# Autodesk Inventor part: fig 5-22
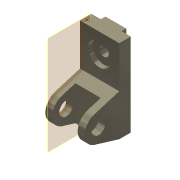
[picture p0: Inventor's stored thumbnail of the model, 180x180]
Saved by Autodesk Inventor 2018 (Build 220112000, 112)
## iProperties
Shininess: 65.0
Angle Display Precision: 2
Document Length Units: 11269
Document Angle Units: 11279
Document Time Units: 11290
Document Mass Units: 11283
Document Length Units Precision: 3
Document Angle Units Precision: 2
Compacted: False
Created: 2001-11
Part Number: fig 5-22
Document SubType Name: Modeling
Designer: Renu Muthoo
Density: 1 g/cm^3
Material: Generic
Appearance: Metal-Titanium (Polished)
Density: 0.0
Volumn: 0.0
Area: 0.0
PropertySet Name: Model Information
Control State: 0
Master: False
Checked Out: False
Author: Renu Muthoo
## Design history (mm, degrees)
node "Sketch1"
sketch "Sketch2"
  geometry: L1 (33.257, 104.664)-(33.257, -75.336); L2 (33.257, -75.336)-(8.257, -75.336); L3 (8.257, -75.336)-(-45.451, -59.045); L4 (-45.451, -1.628)-(8.257, 14.664); L5 (8.257, 14.664)-(8.257, 104.664); L6 (8.257, 104.664)-(33.257, 104.664); C1 r 15 at (-36.743, -30.336); A1 r 30 centre (-36.743, -30.336) between (-45.451, -1.628) and (-45.451, -59.045)
  constraints: 12 end point, 2 centre point, 2 equal length, 2 parallel, 2 point on circle, 2 tangent, 1 coincident, 1 perpendicular, 1 vertical
  dimensions: "d0" = 180 distance of L1.start L1.end; "d1" = 30 radius of A1; "d2" = 25 distance of L5.end L1.start; "d3" = 45 distance from line of L2 A1.centre; "d4" = 70 distance from line of L1 A1.centre; "d5" = 30 diameter of C1
extrude "Extrusion1" new body sketch "Sketch2" distance "d6" = 85; taper "d7" = 0 deg
workplane "Work Plane1"
sketch "Sketch3"
  geometry: L1 (15, 62.364)-(70, 62.364); L2 (70, 62.364)-(70, -52.386); L3 (70, -52.386)-(15, -52.386); L4 (15, -52.386)-(15, 62.364); L5 (0, -45)-(0, -28.708) reference
  constraints: 8 end point, 2 parallel, 1 horizontal, 1 perpendicular
  dimensions: "d8" = 55 distance of L1.start L1.end; "d9" = 15 distance between parallel lines of L5 L4
extrude "Extrusion2" cut sketch "Sketch3" distance "d10" = 50; taper "d11" = 0 deg
sketch "Sketch4"
  geometry: L1 (0, 25)-(85, 25) reference; L2 (0, 0)-(0, 25) reference; L3 (20, 25)-(65, 25); L4 (65, 25)-(65, 35); L5 (65, 35)-(20, 35); L6 (20, 35)-(20, 25)
  constraints: 8 end point, 2 parallel, 1 horizontal, 1 perpendicular, 1 point on line
  dimensions: "d12" = 45 distance of L4.end L5.end; "d13" = 10 distance of L3.end L4.end; "d14" = 20 distance between parallel lines of L2 L6
extrude "Extrusion3" join sketch "Sketch4" stored distance "d15" = 50; taper "d16" = 0 deg
sketch "Sketch5"
  geometry: L1 (85, 0)-(85, 90) reference; L2 (0, 90)-(85, 90) reference; 1 further point
  dimensions: "d17" = 42 distance from line of L2 point (42.5, 48); "d18" = 42.5 distance from line of L1 point (42.5, 48)
hole "Hole1" sketch "Sketch5" at (42.5, 48) diameter "d19" = 20; stored, may be unused: countersink angle "d23" = 82 deg, drill point angle "d25" = 118 deg; dims "d20" = 6, "d21" = 50, "d22" = 10, "d24" = 8
sketch "Sketch11"
  geometry: 1 further point
workplane "Work Plane17"
body "Solid1"
